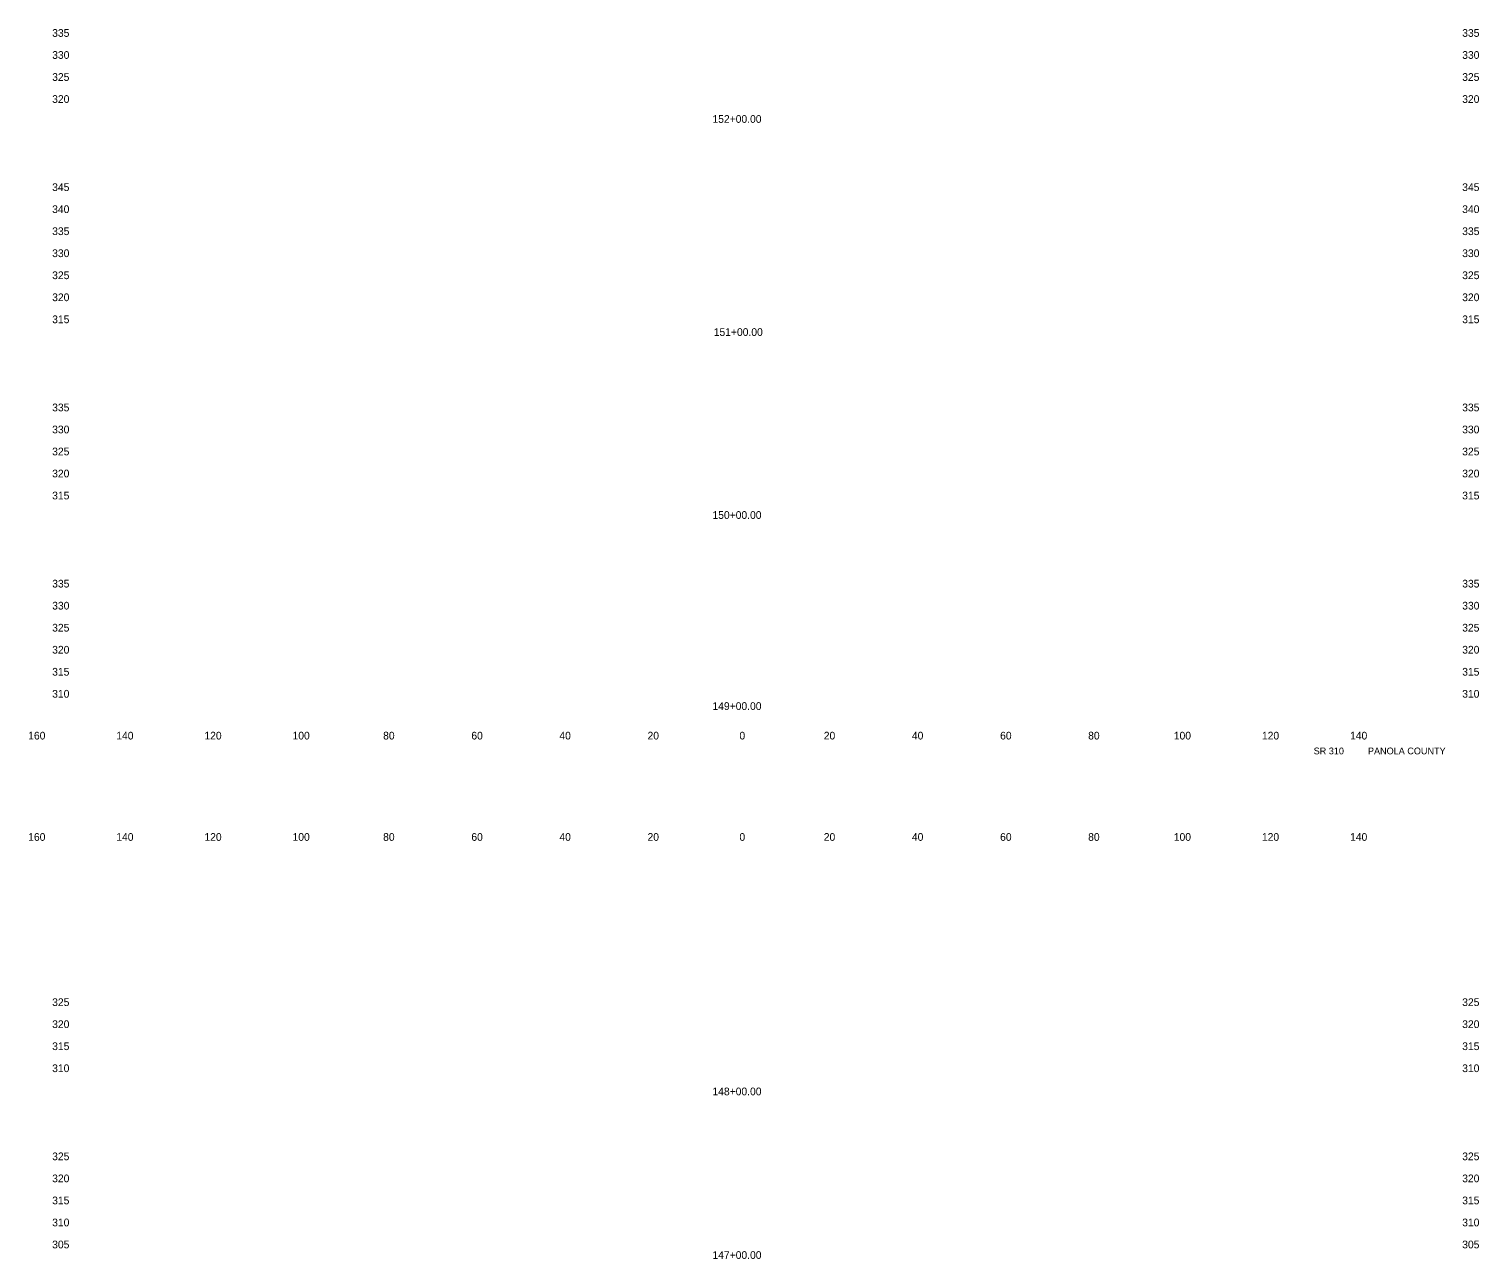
# Model space of a CAD drawing. Extents: x 21481 to 21810, y 6485 to 11067.
# Drawn here: x 21480.9 to 21809.9, y 10510.3 to 10789.5 of the extents above; entities that cross this region are included whole.
import ezdxf

# ---------------------------------------------------------------- set-up
doc = ezdxf.new("R2010")
doc.units = 0
for name, color, linetype in [('62', 7, 'Continuous'), ('XS_CELL', 7, 'Continuous'), ('XS_P_TX_DCH', 7, 'Continuous'), ('XS_P_TX_FS_BS', 7, 'Continuous')]:
    doc.layers.add(name, color=color, linetype=linetype)

msp = doc.modelspace()

# ---------------------------------------------------------------- texts
at = {"layer": '62'}
for s, p in [('  160  ', (21479.4, 10628.21)), ('  140  ', (21499.39, 10628.21)), ('  120  ', (21519.39, 10628.21)), ('  100  ', (21539.39, 10628.21)), ('  80  ', (21559.95, 10628.21)), ('  60  ', (21579.97, 10628.21)), ('  40  ', (21599.95, 10628.21)), ('  20  ', (21619.95, 10628.21)), ('  0  ', (21640.81, 10628.21)), ('  0  ', (21640.81, 10628.21)), ('  20  ', (21659.95, 10628.21)), ('  40  ', (21679.95, 10628.21)), ('  60  ', (21699.97, 10628.21)), ('  80  ', (21719.95, 10628.21)), ('  100  ', (21739.39, 10628.21)), ('  120  ', (21759.39, 10628.21)), ('  140  ', (21779.39, 10628.21)), ('  160  ', (21479.4, 10605.21)), ('  140  ', (21499.39, 10605.21)), ('  120  ', (21519.39, 10605.21)), ('  100  ', (21539.39, 10605.21)), ('  80  ', (21559.95, 10605.21)), ('  60  ', (21579.97, 10605.21)), ('  40  ', (21599.95, 10605.21)), ('  20  ', (21619.95, 10605.21)), ('  0  ', (21640.81, 10605.21)), ('  0  ', (21640.81, 10605.21)), ('  20  ', (21659.95, 10605.21)), ('  40  ', (21679.95, 10605.21)), ('  60  ', (21699.97, 10605.21)), ('  80  ', (21719.95, 10605.21)), ('  100  ', (21739.39, 10605.21)), ('  120  ', (21759.39, 10605.21)), ('  140  ', (21779.39, 10605.21))]:
    msp.add_text(s, height=1.75, dxfattribs=at).set_placement(p)
at = {"layer": 'XS_CELL'}
for s, p in [('  335  ', (21484.84, 10787.71)), ('  335  ', (21804.84, 10787.71)), ('  330  ', (21484.84, 10782.71)), ('  330  ', (21804.84, 10782.71)), ('  325  ', (21484.84, 10777.71)), ('  325  ', (21804.84, 10777.71)), ('  320  ', (21484.84, 10772.71)), ('  320  ', (21804.84, 10772.71)), ('  345  ', (21484.84, 10752.71)), ('  345  ', (21804.84, 10752.71)), ('  340  ', (21484.84, 10747.71)), ('  340  ', (21804.84, 10747.71)), ('  335  ', (21484.84, 10742.71)), ('  335  ', (21804.84, 10742.71)), ('  330  ', (21484.84, 10737.71)), ('  330  ', (21804.84, 10737.71)), ('  325  ', (21484.84, 10732.71)), ('  325  ', (21804.84, 10732.71)), ('  320  ', (21484.84, 10727.71)), ('  320  ', (21804.84, 10727.71)), ('  315  ', (21484.84, 10722.71)), ('  315  ', (21804.84, 10722.71)), ('  335  ', (21484.84, 10702.71)), ('  335  ', (21804.84, 10702.71)), ('  330  ', (21484.84, 10697.71)), ('  330  ', (21804.84, 10697.71)), ('  325  ', (21484.84, 10692.71)), ('  325  ', (21804.84, 10692.71)), ('  320  ', (21484.84, 10687.71)), ('  320  ', (21804.84, 10687.71)), ('  315  ', (21484.84, 10682.71)), ('  315  ', (21804.84, 10682.71)), ('  335  ', (21484.84, 10662.71)), ('  335  ', (21804.84, 10662.71)), ('  330  ', (21484.84, 10657.71)), ('  330  ', (21804.84, 10657.71)), ('  325  ', (21484.84, 10652.71)), ('  325  ', (21804.84, 10652.71)), ('  320  ', (21484.84, 10647.71)), ('  320  ', (21804.84, 10647.71)), ('  315  ', (21484.84, 10642.71)), ('  315  ', (21804.84, 10642.71)), ('  310  ', (21484.84, 10637.71)), ('  310  ', (21804.84, 10637.71)), ('  325  ', (21484.84, 10567.71)), ('  325  ', (21804.84, 10567.71)), ('  320  ', (21484.84, 10562.71)), ('  320  ', (21804.84, 10562.71)), ('  315  ', (21484.84, 10557.71)), ('  315  ', (21804.84, 10557.71)), ('  310  ', (21484.84, 10552.71)), ('  310  ', (21804.84, 10552.71)), ('  325  ', (21484.84, 10532.71)), ('  325  ', (21804.84, 10532.71)), ('  320  ', (21484.84, 10527.71)), ('  320  ', (21804.84, 10527.71)), ('  315  ', (21484.84, 10522.71)), ('  315  ', (21804.84, 10522.71)), ('  310  ', (21484.84, 10517.71)), ('  310  ', (21804.84, 10517.71)), ('  305  ', (21484.84, 10512.71)), ('  305  ', (21804.84, 10512.71))]:
    msp.add_text(s, height=1.75, dxfattribs=at).set_placement(p)
at = {"layer": 'XS_P_TX_DCH'}
for s, p in [('  152+00.00  ', (21634.69, 10768.19)), ('  151+00.00  ', (21634.98, 10719.82)), ('  150+00.00  ', (21634.69, 10678.29)), ('  149+00.00  ', (21634.69, 10634.92)), ('  148+00.00  ', (21634.69, 10547.45)), ('  147+00.00  ', (21634.69, 10510.31))]:
    msp.add_text(s, height=1.75, dxfattribs=at).set_placement(p)
at = {"layer": 'XS_P_TX_FS_BS'}
for s, p in [('SR 310', (21772.43, 10624.84)), ('SR 310', (21772.43, 10624.84)), ('PANOLA COUNTY', (21784.75, 10624.84)), ('PANOLA COUNTY', (21784.75, 10624.84))]:
    msp.add_text(s, height=1.54, dxfattribs=at).set_placement(p)

doc.saveas('drawing.dxf')
